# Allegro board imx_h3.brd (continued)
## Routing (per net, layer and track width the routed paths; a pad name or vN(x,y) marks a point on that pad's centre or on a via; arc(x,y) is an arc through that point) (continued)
USBOTG_OC: length 67.2
  TOP w0.1: v1(46.42,41.59) 47.67,41.59 48.64,42.56 v1(49.38,42.56)
  INT1 w0.1: v1(84.04,18.37) 84.04,19.53 81.65,21.92 69.06,21.92 68.12,22.86 62.09,22.86 62.08,22.85 61.41,22.85 60.7,23.57 59.87,23.57 58.99,23.57 57.17,25.4 56.99,25.4 v1(56.92,25.47)
  BOTTOM w0.1: v1(84.04,18.37) 84.04,16.43 85,15.47 85,13.02 84.94,12.96 ; U1.D4 52.64,43.41 52.36,43.13 51.98,43.13 51.97,43.14 51.65,43.14 51.45,42.94 51.45,42.74 51.13,42.43 50.89,42.43 50.59,42.13 50.59,41.83 50.41,41.65 49.92,41.65 49.55,42.03 49.55,42.4 v1(49.38,42.56) ; v1(46.42,41.59) 46.42,41.07 45.96,40.61 45.96,39.11 46.16,38.91 46.16,37.78 46.17,37.78 46.17,37.15 46.2,37.12 46.2,36.49 46.18,36.48 46.18,36.09 49.73,32.54 50.17,32.54 50.17,32.55 50.56,32.55 51.1,32.55 54.68,28.97 55.45,28.97 56.81,27.61 56.81,25.6 56.92,25.49 v1(56.92,25.47)
USBOTG_VBUS_EN: length 185.3
  TOP w0.1: v1(80.76,10.43) 80.76,19.36 80.16,19.96 80.16,20.17 v1(80.02,20.32) ; v1(36.77,23.81) 36.77,24.12 35.36,25.53 22.11,25.53 21.64,26 18.7,26 17.94,26.76 13.76,26.76 13.35,26.36 v1(13.15,26.36)
  INT1 w0.1: v1(44.72,70.62) 44.72,70.62 44.23,70.13 44.23,69.07 43.5,68.34 43.5,67.68 43.5,66.75 37.95,61.19 37.95,58 37.49,57.55 37.49,57.53 36.32,56.36 35.94,56.36 35.1,56.36 34.6,56.36 34.59,56.37 34.02,56.37 34.01,56.36 32.66,56.36 32.66,56.37 31.83,56.37 30.57,55.11 30.55,55.11 29.21,53.77 28.85,53.77 27.64,52.55 22.57,52.55 21.97,51.96 21.97,50.53 20.76,49.31 20.76,47.92 16.27,43.43 16.27,39.43 14.26,37.43 13.99,37.16 v1(13.99,37.04) 13.99,36.79 13.54,36.33 13.54,30.69 13.67,30.56 13.67,27.09 13.15,26.57 v1(13.15,26.36) ; v1(80.02,20.32) 78.85,21.49 69.31,21.49 68.11,20.28 63.91,20.28 63.58,20.28 63.14,20.73 61.89,20.73 61.45,21.17 39.8,21.17 37.16,23.81 v1(36.77,23.81)
  BOTTOM w0.1: U17.1 69.75,68.24 69.99,68.48 69.99,68.54 70,68.54 70,68.88 69.99,68.89 69.99,69.59 69.71,69.88 69.64,69.88 69.61,69.91 68.15,69.91 67.53,70.53 67.53,71.87 66.39,73.01 47.01,73.01 44.8,70.8 44.8,70.71 v1(44.72,70.62) ; v1(13.99,37.04) 14.07,37.04 14.14,37.12 14.41,37.12 16.23,35.29 16.23,33.99 U40.13 ; v1(80.76,10.43) 80.76,8.79 81,8.55 82,8.55 82.85,7.7 83.55,7.7 83.6,7.75 83.6,8.46 U33.3
VR_ANA: length 1.9
  BOTTOM w0.3: 25.59,66.69 25.56,66.71 C188.1 24.67,66.62 U4.44
VR_DIG: length 3.6
  BOTTOM w0.3: C189.1 27.28,66.32 C167.1 26.29,66.12 U4.45
VR_PA: length 5.3
  BOTTOM w0.3: C176.1 22.68,72.13 22.68,69.99 22.73,69.94 23.05,69.94 23.09,69.88 23.31,69.88 C174.1 23.65,69.52 C173.1 23.16,68.17 U4.42
WIFI_SDIO_CLK: length 8.6
  TOP w0.1: v1(19.44,35.83) 19.45,35.84 19.45,36.77 17.22,39 15.64,39 J20.25
  BOTTOM w0.1: R193.2 19.44,33.26 v1(19.44,35.83)
WIFI_SDIO_CMD: length 7.2
  TOP w0.1: J20.29 17.22,37.3 18.39,36.13 18.39,34.22 v1(18.12,33.95)
  BOTTOM w0.1: R64.2 18.12,34.65 v1(18.12,33.95) 18.12,33.46 R194.2
WIFI_SDIO_D0: length 7.3
  TOP w0.1: J20.23 16.83,39.7 19.25,37.28 19.25,37.28 19.79,36.75 19.79,36.22 v1(20.03,35.97)
  BOTTOM w0.1: v1(20.03,35.97) 20.03,35.05 R195.2
WIFI_SDIO_D1: length 5
  TOP w0.1: v1(18.82,35.88) 18.82,35.99 16.71,38.1 J20.27
  BOTTOM w0.1: v1(18.82,35.88) 18.86,35.88 R196.2
WIFI_SDIO_D2: length 6.9
  TOP w0.1: v1(21.27,36.64) 21.27,36.64 21.27,36.69 22.23,37.64 23.69,37.64 J20.28
  BOTTOM w0.1: R197.2 20.54,33.28 20.54,35.66 21.27,36.41 21.27,36.63 v1(21.27,36.64)
WIFI_SDIO_D3: length 3.9
  TOP w0.1: J20.30 22.13,36.9 21.52,36.28 v1(21.52,36.06)
  BOTTOM w0.1: R198.2 21.14,35.11 21.14,35.69 v1(21.52,36.06)
WL_RF_1V8: length 11
  TOP w0.1: 15.48,47.78 J20.11
  TOP w0.3: J20.11 14.05,47.7 C214.1 C151.1 12.2,48.55 12.2,51.92 13.14,52.87 v1(13.32,52.87)
  BOTTOM w0.3: v1(13.32,52.87) 13.32,53.04 13.7,53.41 U14.5 12.46,53.6 C199.1
WLAN_ACTIVE: length 118
  TOP w0.1: J20.49 14.14,29.3 12.88,30.56 v1(12.47,30.56)
  INT1 w0.1: v1(85.71,79.65) 85.46,79.4 84.09,79.4 82.83,78.15 82.83,75.15 80.38,72.69 79.35,72.69 78.91,72.25 71.95,72.25 71.5,72.69 63.86,72.69 63.86,72.7 62.65,72.7 62.65,72.69 46.26,72.69 45.89,72.33 44.7,72.33 36.7,64.32 36.7,58.29 36.67,58.27 36.67,58 35.83,57.16 34.94,57.16 34.92,57.17 34.34,57.17 34.34,57.18 33.68,57.18 33.66,57.16 33.01,57.16 33,57.16 32.32,57.16 32.32,57.17 31.99,57.17 31.49,57.17 30.23,55.91 30.22,55.91 28.88,54.57 28.52,54.57 27.31,53.35 23.56,53.35 23.06,53.35 22.73,53.35 22.73,53.35 22.22,53.35 21.16,52.29 21.16,50.99 19.95,49.78 19.95,48.25 12.76,41.06 12.76,40.75 12.74,40.74 12.74,33.24 12.43,32.92 12.43,30.62 v1(12.47,30.56)
  BOTTOM w0.1: R110.1 87.9,84.89 87.9,83 86.35,81.45 86.35,80.29 v1(85.71,79.65)
WLAN_PDN: length 79.5
  TOP w0.1: J20.22 24.85,40.1 26.75,42 26.75,50.28 28.56,52.1 28.68,52.23 28.73,52.28 v1(28.73,52.44)
  BOTTOM w0.1: U17.6 68.84,64.58 67.7,63.45 64.69,63.45 60.62,67.51 60.62,69.87 59.29,71.2 49.28,71.2 47.66,69.57 46.81,69.57 45.73,68.49 45.53,68.49 45.49,68.49 45.45,68.51 45.4,68.53 45.39,68.53 45.08,68.53 45.05,68.52 45.01,68.5 44.96,68.49 42.58,68.49 40.19,70.88 39.14,70.88 39.08,70.83 36.87,70.83 35.84,69.81 35.6,69.81 35.52,69.73 33.33,69.73 29.6,66 29.6,65.94 29.51,65.84 29.51,65.82 29.49,65.81 29.49,58.58 29.13,58.22 28.55,57.64 28.55,56.63 27.69,55.76 27.69,53.76 28.73,52.71 v1(28.73,52.44)
WLAN_WAKE: length 76.6
  TOP w0.1: v1(13.99,40.6) 14.11,40.6 14.21,40.5 J20.21
  INT1 w0.1: v1(13.99,40.6) 13.99,41.44 20.55,48.01 20.55,49.4 21.77,50.61 21.77,51.87 21.77,51.88 21.77,52.04 22.48,52.75 22.98,52.75 27.56,52.75 28.77,53.97 29.13,53.97 30.47,55.31 30.48,55.31 31.74,56.57 32.08,56.57 32.08,56.56 32.74,56.56 32.75,56.56 33.92,56.56 33.94,56.57 34.09,56.57 34.09,56.57 34.67,56.57 34.68,56.56 35.18,56.56 35.52,56.56 36.24,56.56 37.29,57.61 37.29,57.63 37.74,58.08 37.74,61.34 43.3,66.9 43.3,67.6 43.3,67.6 43.3,68.48 44.03,69.22 44.03,70.54 44.94,71.44 47.32,71.44 v1(47.7,71.06)
  BOTTOM w0.1: v1(47.7,71.06) 47.7,71.09 48.62,72 59.3,72 59.31,72 59.63,72 60.84,70.78 61.52,70.11 61.52,67.84 64.32,65.03 U17.12
ZB_SPI_MISO: length 46.8
  INT1 w0.1: v1(84.94,56.94) 84.94,56.94 85.47,56.4 86.3,56.4 88.1,54.6 88.1,52.34 88.11,52.34 88.11,50.09 93.84,44.35 95.1,44.35 96.12,45.37 v1(97.56,45.37)
  BOTTOM w0.1: RN8.2 75.68,73.12 77.23,71.57 77.23,70.75 79.86,68.12 79.86,66.71 80.22,66.34 80.22,66.28 80.23,66.28 80.23,65.59 80.22,65.59 80.22,64.99 81.29,63.92 81.29,60.88 84.94,57.23 v1(84.94,56.94) ; U15.29 102.03,44.6 101.8,44.84 100.76,44.84 100.1,45.49 U15.34 98.8,45.49 98.69,45.37 v1(97.56,45.37)
ZB_SPI_MOSI: length 47.6
  INT1 w0.1: v1(84.6,56.05) 84.85,55.8 85.3,55.8 85.6,55.5 86.6,55.5 87.7,54.4 87.7,52.12 87.71,52.12 87.71,49.92 93.7,43.93 95.4,43.93 95.78,44.3 96.9,44.3 98.45,42.75 99.16,42.75 99.18,42.76 v1(99.65,42.76)
  BOTTOM w0.1: RN8.4 76.04,72.12 76.81,71.35 76.81,70.59 79.45,67.95 79.45,66.84 79.46,66.54 79.82,66.18 79.82,66.11 79.83,66.1 79.83,65.76 79.82,65.76 79.82,65.56 79.82,64.83 80.89,63.76 80.89,60.71 84.14,57.46 84.14,56.71 84.6,56.25 v1(84.6,56.05) ; U15.28 102.5,44.1 102.5,43.81 101.45,42.76 v1(99.65,42.76)
ZB_SPI_SCK: length 49
  INT1 w0.1: v1(102.37,43.11) 102.34,43.11 99.92,45.54 98.04,45.54 97.7,45.88 96.33,45.88 95,44.55 93.93,44.55 88.31,50.17 88.31,52.42 88.3,52.43 88.3,54.75 86.45,56.6 86,56.6 85.59,57.01 v1(85.54,57.01)
  BOTTOM w0.1: RN8.1 75.64,73.62 77.43,71.84 77.43,70.84 80.06,68.21 80.06,66.79 80.42,66.43 80.42,66.37 80.43,66.36 80.43,65.51 80.42,65.5 80.42,65.07 81.49,64 81.5,64 81.5,63.84 81.49,63.84 81.49,60.96 85.44,57.01 v1(85.54,57.01) ; U15.27 103.03,43.77 v1(102.37,43.11)
ZB_SPI_SS: length 46.3
  INT1 w0.1: v1(85.85,55.95) 86.45,55.95 87.9,54.5 87.9,52.26 87.91,52.26 87.91,50 93.78,44.12 95.25,44.12 95.68,44.55 96.95,44.55 98.05,43.45 98.76,43.45 98.77,43.47 v1(99.22,43.47)
  BOTTOM w0.1: RN8.3 75.9,72.62 77.01,71.5 77.01,70.68 79.66,68.03 79.66,67.25 79.65,67.25 79.65,66.92 79.66,66.62 79.9,66.38 79.9,66.38 80.02,66.26 80.02,66.19 80.03,66.19 80.03,65.68 80.02,65.68 80.02,65.48 80.02,65.48 80.02,64.91 81.09,63.84 81.09,60.79 84.48,57.41 84.48,56.82 85.35,55.95 v1(85.85,55.95) ; v1(99.22,43.47) 99.66,43.47 99.77,43.57 101.46,43.57 101.53,43.65 U15.30
ZIGBEE_FLASH_ERASE: length 62.7
  TOP w0.1: v1(93.98,45.24) 92.65,45.24 91.4,46.5 91,46.5 88.79,48.7 85.4,48.7 82.2,51.9 82.2,57.6 81.15,58.65 v1(81.15,59.15)
  BOTTOM w0.1: v1(93.98,45.24) 94.1,45.36 95.71,45.36 96.79,44.28 96.8,44.28 97.8,43.28 97.8,42 98.6,41.2 104.5,41.2 104.78,41.48 106.72,41.48 107.51,42.26 108.98,42.26 110.43,43.71 110.86,43.71 110.96,43.81 111.14,43.81 111.56,44.24 111.56,44.62 111.88,44.94 112.93,44.94 R145.1 ; v1(81.15,59.15) 80.9,58.9 79.75,58.9 74.39,64.26 74.39,64.93 71.37,67.95 70.94,67.95 70.76,68.12 69.96,68.12 69.57,67.74 U17.2
ZIGBEE_GPIO: length 98.6
  TOP w0.1: v1(57.11,44.03) 57.02,44.03 56.69,43.71 56.69,42.91 56.89,42.71 56.89,41.91 56.23,41.25 55.71,41.25 54.86,40.4 53.35,40.4 50.14,37.19 44.91,37.19 v1(44.88,37.22)
  INT1 w0.1: v1(98.73,44.63) 99.66,44.63 100.07,44.22 100.07,42.46 98.5,40.89 98.5,39.67 v1(96.25,37.42) ; v1(89.3,24.11) 88.45,24.11 87.92,23.58 84.18,23.58 83.44,24.32 61.98,24.32 60.86,25.44 v1(60.73,25.44)
  BOTTOM w0.1: U15.33 98.94,44.98 98.73,44.78 v1(98.73,44.63) ; v1(57.11,44.03) 57.05,44.03 U1.E9 ; v1(89.3,24.11) 89.3,34.44 91.35,36.49 95.32,36.49 v1(96.25,37.42) ; v1(44.88,37.22) 45.1,37.22 45.59,36.75 45.59,35.83 49.47,31.94 50.41,31.94 50.41,31.95 50.8,31.95 54.41,28.34 54.7,28.34 55.46,27.57 55.46,27.13 55.99,26.6 55.99,26.59 56.52,26.06 56.52,25.25 56.8,24.97 60.27,24.97 v1(60.73,25.44)
ZIGBEE_LED: length 66.8
  TOP w0.1: v1(85.7,78.3) 85.55,78.45 84,78.45 83.75,78.2 83.75,76.05 82.45,74.75 82.45,58.7 82.1,58.35 82.1,58 82.45,57.65 82.45,51.95 85.5,48.9 89,48.9 91.15,46.75 91.55,46.75 91.8,46.5 v1(92.8,46.5)
  BOTTOM w0.1: R102.1 90.35,86.48 90.35,85 88.9,83.55 88.9,83.3 86.9,81.3 86.9,79.35 85.85,78.3 v1(85.7,78.3) ; U15.26 103.53,43.13 102.65,42.25 98.8,42.25 98.65,42.4 98.65,43.4 95.9,46.15 93.1,46.15 93,46.25 93,46.3 v1(92.8,46.5)
ZIGBEE_RESET_B: length 66
  TOP w0.1: v1(77.4,59.92) 77.4,59.6 81.05,55.95 81.05,51.15 83.77,48.44 83.77,48.43 83.81,48.38 83.81,48.38 83.99,48.2 84,48.2 85.09,47.1 87.5,47.1 88.54,46.06 R146.2 ; v1(103.59,54.09) 103.66,54.16 104.23,54.16 106.78,51.62 106.78,46.75 102.21,42.17 98.51,42.17 97.58,43.1 96.15,43.1 95.22,44.03 91.15,44.03 90.62,44.55 89.55,44.55 88.92,45.18 R146.2 ; R146.2 R80.1
  BOTTOM w0.1: v1(77.4,59.92) 76.83,59.92 70.51,66.24 U17.5 ; v1(103.59,54.09) 103.48,54.19 101.95,54.19 101.57,53.81 101.57,53.36 U15.51
N20112384: length 11.8
  BOTTOM w0.3: R82.2 92.75,51.98 C156.1 93.79,52.26 L10.2 ; L10.2 98.06,50.49 U15.44 ; L10.2 96.5,52.46 96.5,55.18 C184.1
N20121042: length 13.1
  TOP w0.3: v1(92.71,51.04) 92.71,53.22 93.94,54.45 v1(93.94,54.53)
  BOTTOM w0.3: v1(93.94,54.53) 94.15,54.32 D6.A ; v1(92.71,51.04) 92.71,50.57 93.21,50.07 93.29,50.07 94.04,49.32 96.25,49.32 L10.1 96.91,49.99 U15.43
N20123696: length 6.1
  BOTTOM w0.3: U15.45 99.08,50.99 98.64,51.43 98.64,53.73 D6.C 98.05,54.43 97.5,54.99 97.5,55.79 97.55,55.85
N20135512: length 14
  TOP w0.1: v1(106.94,54.32) 106.94,54.25 106.59,53.9 106.59,52.81 111.02,48.38 v1(111.65,48.38)
  BOTTOM w0.1: R76.1 113.2,46.25 R145.2 ; R76.1 112.39,47.3 Q4.1 112.48,47.49 111.77,48.2 111.77,48.25 v1(111.65,48.38) ; R76.1 R75.1 ; U15.61 106.59,53.38 106.59,53.9 107.01,54.32 v1(106.94,54.32)
N20137474: length 6.4
  BOTTOM w0.1: U15.64 108.94,53.33 109.36,52.91 109.36,51.36 R77.1 109.96,50.8 111.32,49.44 111.68,49.44 Q4.3
N20150953: length 1.6
  BOTTOM w0.3: J12.1 106.33,66.26 C182.2
N20151194: length 10.4
  BOTTOM w0.3: U15.60 106.04,54.68 106.04,63.06 106.06,63.17 106.07,63.25 106.16,63.46 106.18,63.48 C181.1
N20157126: length 5.4
  BOTTOM w0.1: 101.21,58.23 100.46,57.48 100.46,54.96 100.87,54.54 100.87,53.5 U15.50
N20157653: length 3.1
  BOTTOM w0.1: Y5.3 100.2,55.44 100.2,54.7 100.53,54.37 U15.49
N20183643: length 13.7
  TOP w0.1: v1(41.58,46.25) v1(41.58,47.47)
  BOTTOM w0.1: R181.2 44.83,47.47 44.82,47.48 44.43,47.48 44.42,47.47 43.82,47.47 43.81,47.48 43.42,47.48 43.41,47.47 v1(41.58,47.47) 41.56,47.48 41.36,47.48 41.08,47.2 38.27,47.2 38.19,47.27 37.36,47.27 36.77,47.87 35.3,47.87 35.09,47.66 U3.12 ; v1(41.58,46.25) 41.54,46.21 R9.2
N20200163: length 8.5
  BOTTOM w0.1: 50.8,16.94 50.8,20.18 R6.2 52.51,20.34 C31.1 ; 50.8,16.94 50.8,16.25 52.02,15.03 T1.5 ; 50.8,16.94 T1.4
N20614471: length 2.2
  BOTTOM w0.3: C177.1 21.66,72.9 21.66,72.16 21.67,72.15 L6.2 21.67,71.39 L7.2
N20623476: length 1.5
  BOTTOM w0.3: L8.1 21.68,75.41 C194.1 21.66,74.65 C177.2
N20623914: length 1.5
  BOTTOM w0.3: L8.2 21.67,77.17 C179.1 21.67,77.91 L9.1
N20639994: length 1.5
  BOTTOM w0.3: 21.68,78.93 21.68,79.67 C180.1 21.67,80.41 C193.1
N20766165: length 1.4
  BOTTOM w0.1: R15.1 31.7,42.37 U3.24
N20769333: length 4
  BOTTOM w0.3: C33.1 30.46,47.48 C32.1 31.37,48.19 31.56,47.99 31.56,47.54 31.62,47.49 31.62,46.72 U3.6
N20787959: length 5.6
  BOTTOM w0.3: 62.24,41.24 62.24,40.95 62.24,40.95 62.24,39.84 62.24,39.84
  BOTTOM w0.5: 62.24,39.84 62.52,39.56 62.52,38.9 63.25,38.16 L2.1
N20788242: length 8.7
  BOTTOM w0.3: 63.48,40.38 63.48,41.6 63.05,42.03
  BOTTOM w0.35: 66.36,38.05 65.25,38.05 64.3,39 63.65,39 63.2,39.45 63.2,40.1 63.48,40.38
  BOTTOM w0.5: L2.2 66.65,37.76 66.36,38.05
N21052242: length 6.8
  TOP w0.1: v1(55.98,40.39) 55.89,40.39 55.3,39.8 54.61,39.8 54.24,39.8 53.92,39.48 53.92,38.98 53.52,38.57 53.52,38.48 R49.1
  BOTTOM w0.1: U1.B9 56.64,41.97 56.17,41.5 56.17,40.58 55.98,40.39 v1(55.98,40.39)
N21053866: length 6.9
  BOTTOM w0.1: 55.61,36.31 Y3.1 56.38,37.08 C142.2 56.5,37.57 56.97,38.04 57.69,38.04 58.45,38.8 58.58,38.8 58.92,39.14 58.92,40.01 59.03,40.11 59.03,40.16 59.05,40.18 59.05,41.24
N21053884: length 8.2
  BOTTOM w0.1: 59.05,42.03 59.35,41.73 59.35,40.2 59.23,40.08 59.23,40.03 59.12,39.93 59.12,37.65 C141.1 58.88,37.34 58.88,35.15 58.64,34.92 Y3.3
N21906184: length 22.6
  TOP w0.3: 11.59,10.88 11.59,9.69 11.62,9.66 ; 11.59,10.88 11.59,11.96 11.64,12.01 ; 11.59,10.88 8.66,10.88 8.59,10.82 ; 11.59,10.88 J5.1 ; J5.1 14.51,10.88 14.52,10.9 ; J5.1 11.88,11.8 ; J5.1 11.88,9.97
  TOP w0.4: F1.2 13.66,17.42 ; F1.2 14.61,16.77 ; F1.2 12.71,16.77 ; F1.2 13.66,16.12 ; 15.01,16.7 C107.1 ; C107.1 15.61,17.61 ; C107.1 15.61,15.79
  PWR w0.3: J5.1 11.88,11.8 ; J5.1 11.88,9.97 ; J5.1 9.38,10.88 ; J5.1 14.39,10.88
  vias: v1(7.69,9.59) v1(7.68,5.92) v1(7.68,2.16) v1(11.1,13.88) v1(11.1,12.88) v1(11.59,7.99) v1(11.58,2.04) v1(12.1,17.3) v1(15.1,14.88) v1(15.1,12.88) v1(15.28,9.44) v1(15.45,5.74) v1(15.45,2.03) v1(15.82,11.38) v1(15.9,14.05)
N22010545: length 1.5
  BOTTOM w0.1: 106.19,42.82 106.19,42.87 106.56,43.24 106.56,44.11 U15.20
N22878041: length 0.8
  TOP w0.1: R41.2 65.52,18.42 C108.2
N22880531: length 22.6
  TOP w0.1: R41.1 66.44,20.19 66.46,20.21 66.51,20.21 67.37,19.34 67.52,19.34 67.67,19.19 67.67,15.51 70.2,12.99 70.2,2.04 SW2.1
N24090083: length 14
  TOP w0.1: v1(53.53,36.59) 53.54,36.58 55.45,36.58 56.98,38.11 56.98,38.48 56.96,38.5 56.96,39.07 57.27,39.37 57.27,40.91 57.78,41.43 57.78,42.86 57.91,42.99 v1(57.91,43.22)
  BOTTOM w0.1: U1.D11 58.24,43.56 v1(57.91,43.22) ; v1(53.53,36.59) 52.6,37.51 Y2.1 50.5,37.51 C143.1
N24109192: length 13.6
  TOP w0.1: v1(53.49,35.77) 53.49,35.81 54.06,36.38 55.53,36.38 57.41,38.26 v1(57.41,38.44)
  BOTTOM w0.1: v1(53.49,35.77) 53.49,35.72 52.78,35.01 Y2.2 51.89,34.93 50.32,34.93 C144.1 ; v1(57.41,38.44) 57.37,38.48 57.37,38.85 57.73,39.21 57.73,41.09 57.75,41.11 57.75,41.36 57.73,41.38 57.73,41.89 57.75,41.91 57.75,42.27 58.24,42.76 58.24,42.84
N24612024: length 2.9
  BOTTOM w0.3: ANT1.1 110.16,63.68 C181.2
N25260991: length 6
  TOP w0.3: 118,18.59 117.5,18.09 C304.1 ; 118,18.59 119.37,18.59 J7.1 ; 118,18.59 116.15,18.59 115.6,18.05 L3.2
N25368576: length 1.9
  BOTTOM w0.1: R78.2 108.17,44.26 U15.17
N25879518: length 7.8
  BOTTOM w0.3: C193.2 19.54,80.44 L30.1 arc(17.08,79.43) 16.06,76.98 J10.1
N25882006: length 98.2
  BOTTOM w0.1: 21.64,81.63 21.64,81.62 C191.1
  BOTTOM w0.3: C192.1 23.49,80.51 23.49,82.04 23.44,82.09
  BOTTOM w1: 23.44,82.09 arc(23.74,82.8) 24.44,83.09 46.15,83.09 arc(49.18,84.34) 50.43,87.36 50.43,89.03 arc(49.13,92.16) 46,93.46 13.12,93.46 arc(9.91,92.13) 8.58,88.92 8.58,87.73 arc(10.02,84.26) 13.49,82.82 20.44,82.82 arc(21.29,82.47) 21.64,81.63
N25942077: length 1.2
  BOTTOM w0.1: R125.1 109.08,48.98 U15.8
N26302633: length 5.9
  BOTTOM w0.1: U19.25 99.5,33.19 96.75,30.44 96.75,29.97 96.36,29.58 96.36,29.32 R199.2
N26303165: length 5.6
  BOTTOM w0.1: U19.26 99.43,33.69 96.28,30.54 R200.2
N26303698: length 7.3
  BOTTOM w0.1: 101.31,32.54 101.31,32.07 101.15,31.91 100.73,31.91 R201.2
N26304232: length 6.3
  BOTTOM w0.1: R202.2 96.86,28.34 100.81,32.3 U19.24
N26306493: length 9
  BOTTOM w0.1: U19.21 102.31,32.03 101.99,31.71 100.93,31.71 96.79,27.58 96.79,27.12 R203.2
N26311614: length 7.1
  TOP w0.3: v1(103.81,38.55) 103.76,38.59 103.01,38.59 102.81,38.39 102.81,38.05 102.47,37.71 102.47,35.46 L12.2
  BOTTOM w0.3: v1(103.81,38.55) 103.76,38.59 103,38.59 102.8,38.79 ; U19.5 102.8,37.35 102.8,38.28 102.81,38.29 102.81,38.59 102.82,38.6 102.82,38.72 102.8,38.74 102.8,38.79 ; 102.8,38.79 C61.1
N26315679: length 3
  TOP w0.3: R128.2 100.53,35.74 v1(99.28,35.74)
  BOTTOM w0.3: U19.30 99.33,35.69 v1(99.28,35.74)
N26322683: length 1
  BOTTOM w0.3: C68.1 103.86,32.49 U19.18
N26324953: length 1.1
  BOTTOM w0.3: C82.1 105.66,36.19 U19.10
N26335790: length 7.6
  TOP w0.3: v1(105.73,34.94) 105.81,34.85 105.81,28.56 TP12.1
  BOTTOM w0.3: v1(105.73,34.94) 105.73,34.97 105.51,35.19 U19.12
N26335836: length 7.2
  BOTTOM w0.3: TP11.1 107.24,39.71 107.24,36.86 106.07,35.69 U19.11
N26352753: length 5.9
  BOTTOM w0.1: R134.1 95.05,38.08 R129.1 97.97,38.08 99.86,36.19 U19.31
N26353356: length 2.7
  BOTTOM w0.1: R130.1 99.68,39.01 99.49,38.83 99.49,37.56 100.16,36.89 U19.32
N27366059: length 1.1
  TOP w0.3: R42.1 69.72,40 C104.2
N27773305: length 10.9
  BOTTOM w0.1: 94.06,11.03 U20.6 ; U20.6 94.06,11.68 ; U20.6 93.58,11.35
  BOTTOM w0.3: 92.39,11.25 D12.A ; D12.A 91.6,11.91 ; D12.A 93.17,11.91 ; D12.A 92.39,12.19 L20.2 ; L20.2 93.75,14.67 ; L20.2 95.3,13.56 ; L20.2 93.75,12.44 ; L20.2 92.2,13.56
N27773317: length 2.5
  BOTTOM w0.1: U20.4 95.03,8.49 R132.2 95.81,8.16
N28006980: length 8.5
  TOP w0.1: Q14.3 76.43,35.53 v1(75.2,35.53) ; v1(72.07,34.22) 72.04,34.19 Q13.3
  BOTTOM w0.1: U30.4 76.25,34.38 75.2,35.43 v1(75.2,35.53) 74.52,35.53 73.63,36.42 Q9.1 73.5,36.34 73.5,36.09 72.03,34.63 72.03,34.25 v1(72.07,34.22)
N28006984: length 11.4
  TOP w0.3: Q6.5 74.61,31.76 Q5.5 ; Q6.5 Q6.6 Q6.1 Q6.2 Q6.5 ; Q5.5 Q5.2 Q5.1 Q5.6 Q5.5
N28007052: length 13.3
  TOP w0.1: Q13.6 74.51,34.26 Q14.6
  TOP w0.3: Q13.5 Q13.2 Q13.1 Q13.6 Q13.5 ; Q13.5 74.5,34.84 Q14.5 ; Q14.5 Q14.6 Q14.1 Q14.2 Q14.5
N28007071: length 12.8
  TOP w0.1: Q5.3 71.2,31.41 71.18,31.41 70.95,31.65 70.92,31.65 v1(70.83,31.73) ; v1(75.3,32.36) 76.48,32.36 Q6.3
  BOTTOM w0.1: R135.2 71.44,35.53 ; 71.44,35.53 Q9.3 ; 71.44,35.53 71.2,35.29 70.81,35.29 70.53,35.02 70.53,32.03 v1(70.83,31.73) 70.83,31.65 71,31.48 74.81,31.48 75.3,31.97 v1(75.3,32.36)
N28007120: length 2.1
  TOP w0.3: C204.1 79.32,33.26 79.48,33.43 v1(79.75,33.43)
  BOTTOM w0.3: v1(79.75,33.43) 79.62,33.55 U22.2
N28007130: length 9.2
  TOP w0.3: 78.32,33.88 78.32,33.5 C204.2 ; 78.32,33.88 78.91,34.47 79.52,34.47 D17.C ; 78.32,33.88 v1(78.32,33.92)
  BOTTOM w0.3: v1(78.32,33.92) 78.32,31.73 77.8,31.22 L16.1 78.43,31.84 78.43,33.7 79.1,34.38 79.1,34.7 U22.3
N28007178: length 3.6
  TOP w0.1: v1(78.05,38.5) 78.25,38.71 79.1,38.71 v1(79.16,38.76)
  BOTTOM w0.1: R149.2 78.05,38.79 v1(78.05,38.5) ; v1(79.16,38.76) 79.17,38.74 79.46,38.74 79.62,38.57 U22.9
N28007224: length 1.9
  BOTTOM w0.1: R149.1 77.76,40.25 79.26,40.25 C203.1
N28007244: length 4.7
  TOP w0.1: v1(80.9,41.15) 80.9,40.52 80.93,40.49
  BOTTOM w0.1: U22.10 80.12,38.06 80.34,38.27 80.34,38.79 81,39.44 81,41.04 v1(80.9,41.15)
N28007274: length 4.3
  TOP w0.1: v1(78.73,39.81) 79.29,40.37 79.31,40.37 79.41,40.47 R176.1 80.18,40.48 80.19,40.49
  BOTTOM w0.1: U22.8 79.12,38.2 78.75,38.58 78.75,38.93 78.87,39.04 78.87,39.68 v1(78.73,39.81)
N28567011: length 2.6
  BOTTOM w0.5: U28.5 22.11,39.96 L18.1
N28574144: length 2.9
  BOTTOM w0.5: U28.3 16.28,41.87 16.2,41.94 15.29,41.94 14.82,41.47 14.82,41.28 R172.2
N28583550: length 5.1
  BOTTOM w0.5: C219.2 18.88,43.1 R173.1 ; R173.1 19.61,43.16 19.61,43.56 19.95,43.91 C218.1 21.37,43.9 R174.2 ; R173.1 19.55,43.1 19.55,41.88 U28.4
N28633938: length 9.1
  TOP w0.5: 30.68,64.58 31.03,64.23 R175.1 C224.2 ; 30.68,64.58 30.74,64.58 30.87,64.45 30.93,64.41 31.14,64.2 31.14,63.94 30.95,63.74 R178.2 30.95,62.57 C223.1 ; 30.68,64.58 v1(30.64,64.58) ; v1(34.16,63.49) 33.89,63.76 U29.4
  BOTTOM w0.5: v1(30.64,64.58) 30.74,64.48 30.74,63.95 31.2,63.49 v1(34.16,63.49)
N28634078: length 2.6
  TOP w0.5: L19.1 35.25,63.71 U29.5
N28722713: length 5.1
  BOTTOM w0.5: 28.2,17.29 28.2,18.2 L21.2 28.85,18.85 C303.1 ; 28.2,17.29 28.19,17.3 ; 28.2,17.29 28.2,16 27.69,15.49 J22.A1
N28726188: length 8
  BOTTOM w0.1: C146.2 38.49,34.99 38.4,34.9 38.4,34.03 38.2,33.84 36.19,33.84 35.5,33.15 ; U25.32 35.05,32.7 35.5,33.15 ; R205.1 35.5,33.15
N28726198: length 5.8
  BOTTOM w0.1: 35.45,32.2 35.9,32.65 36.75,32.65 Y7.3 38.06,31.43 C145.1 ; 35.45,32.2 33.33,32.2 U25.33 ; 35.45,32.2 35.46,32.2 R205.2
N28726415: length 3
  BOTTOM w0.3: U25.35 33.89,31.2 34.13,30.97 34.13,30.31 34.79,29.65 R177.1
N28726934: length 2.1
  BOTTOM w0.1: 27.34,32.7 U25.14
  BOTTOM w0.3: 27.34,32.7 27.15,32.5 26.14,32.5 25.94,32.71 C225.1
N28727026: length 1.9
  BOTTOM w0.3: U25.34 34.11,31.7 C226.1
N28727439: length 3.1
  BOTTOM w0.1: U25.25 31.55,36.58 32.14,37.17 32.14,37.51 R137.2 32.14,38.28 R136.1
N28728688: length 3.5
  BOTTOM w0.1: R147.1 34.23,37.29 34.23,37.16 33.84,36.76 R138.2 33.84,36.62 33.84,35.49 33.32,34.97 33.32,34.71 U25.28
N28737757: length 4.3
  TOP w0.5: v1(84.59,14.97) 84.77,14.79 84.77,13.56 D4.A
  BOTTOM w0.3: v1(84.59,14.97) 84.55,14.97 84.35,14.77 84.35,13.02 84.29,12.96
N28745352: length 3.3
  TOP w0.1: J13.77 J13.75 J13.73
  TOP w0.3: R93.1 101.66,73.16 J13.73
N28745357: length 2
  TOP w0.1: 103.61,84.08 103.55,84.14 101.63,84.14
N28753815: length 3.4
  TOP w0.1: D7.C 103.59,16 103.59,15.16 102.88,14.45 102.88,14.36 102.49,13.97 U34.7
N28753820: length 2.9
  TOP w0.1: D8.C 105.48,15.84 103.96,14.31 U34.5
N28753851: length 1.7
  TOP w0.1: R68.2 103.68,18.65 D7.A
N28753854: length 1.6
  TOP w0.1: D8.A 105.48,18.65 R69.2
N28755364: length 3.1
  TOP w0.3: U34.2 105.91,14.54 106.15,14.78 107.32,14.78 C34.1 R19.2
N28758461: length 6.2
  TOP w0.3: L5.2 115.04,4.65 116.01,5.62 116.02,5.62 116.19,5.79 v1(117.05,5.79) 117.32,5.52 J8.1
  BOTTOM w0.3: v1(117.05,5.79) 117.63,5.79 C305.1
N28758635: length 1.1
  TOP w0.3: U34.10 101.41,11.19 R18.2
N28759486: length 2.9
  TOP w0.1: TP15.1 108.89,13.96 U34.1
N28759489: length 4
  TOP w0.1: TP16.1 106.87,16.84 106.43,16.84 106.23,16.64 106.23,15.67 105.26,14.7 U34.3
N28774283: length 5.9
  TOP w0.15: J8.2 117.97,5.97 117.56,6.38 115.23,6.38 114.55,5.7 114.07,5.7 L34.2
N28774290: length 6.3
  TOP w0.15: L34.3 114.12,6.64 117.66,6.64 118.62,5.68 J8.3
N28783725: length 2.6
  BOTTOM w0.1: R95.1 R141.1 31.05,36.59 U25.24
N28784781: length 3
  BOTTOM w0.1: 28.33,37.13 29.06,37.13 29.06,36.79 29.62,36.23 29.89,36.23 30.05,36.07 U25.22
N28787165: length 7.2
  BOTTOM w0.5: L24.2 80.83,16.42 79.52,16.42 78.74,15.64 C301.1 78.25,14.27 76.92,12.94 U35.1
N28847997: length 0.7
  BOTTOM w0.1: U40.10 U40.11
N28848006: length 6
  BOTTOM w0.1: U40.9 13.6,33.89 13.6,28.1 U40.6
N28853722: length 6.1
  BOTTOM w0.1: 25.39,31.41 27,31.41 27.29,31.7 U25.12 ; 25.39,31.41 25.5,31.3 25.5,30.51 R108.1 ; 25.39,31.41 24.35,31.41 24.23,31.28 24.23,30.46 U31.2
N28858706: length 8.1
  TOP w0.1: SW5.1 91.36,2.15 91.36,5.05 89.45,6.95 R144.2
N28858725: length 7.4
  TOP w0.1: SW7.1 SW7.3 106.94,100.8 R127.2
N28859319: length 8.2
  TOP w0.1: R153.1 99.9,6.53 100.17,6.53 102.44,4.26 102.44,2.41 100.98,0.96 SW8.2
N28870429: length 6.2
  BOTTOM w0.3: D11.A 88.82,49.5 L11.2 88.11,49.6 U16.6
N28870443: length 2.1
  BOTTOM w0.3: R98.2 88.28,55.82 R103.1 88.11,55.73 U16.4
N28879486: length 27.1
  TOP w0.1: R121.2 90.62,70.49 90.3,70.81 90.09,70.81 90.09,70.82 v1(90.09,70.82) 90.08,70.81 89.87,70.81 89.54,70.49 R118.2 ; v1(93.87,87.92) 93.87,88.18 96.17,90.48 S1.2
  BOTTOM w0.1: v1(90.09,70.82) 90.09,70.82 90.07,70.84 90.07,77.5 90.56,77.99 90.56,82.26 91.05,82.75 91.05,82.75 91.54,83.24 91.54,85.56 93.65,87.67 93.65,87.7 v1(93.87,87.92)
N28886082: length 6.1
  BOTTOM w0.5: J22.B1 27.69,11.57 28.9,10.35 C302.1 29.84,9.51 30.3,9.05 L22.2
N28952872: length 88.5
  TOP w0.3: v1(86.23,102.47) 85.3,102.47 D38.1 D38.2 D37.1 D36.2 D35.1 D35.2 D42.1 D41.1 D41.2 D40.1 D40.2 D39.1 D39.2 11.26,102.72 11.23,102.7 10.82,102.7 D3.2
  BOTTOM w0.3: C296.1 86.22,90.55 L15.1 86.32,102.39 v1(86.23,102.47)
N28956999: length 38.5
  TOP w0.1: RN6.16 87.04,90.83 87.04,96.27 83.97,99.34 76.3,99.34 75.64,99.34 75.08,99.9 75.03,99.9 74.83,100.1 74.26,100.1 74.06,100.3 73.38,100.3 67.53,100.3 65.89,100.3 65.69,100.5 65.12,100.5 64.72,100.9 64.09,100.9 63.1,100.9 62.77,100.9 61.46,100.9 57.73,100.9 57.53,100.7 56.76,100.7 56.3,101.16 D35.4
N28957279: length 37.9
  TOP w0.1: RN6.15 87.59,90.83 87.59,96.04 86.98,96.65 86.94,96.65 84.05,99.54 76.22,99.54 75.72,99.54 75.16,100.1 75.11,100.1 74.91,100.3 74.34,100.3 74.14,100.5 73.46,100.5 67.61,100.5 67.61,100.5 66.92,100.5 65.97,100.5 65.77,100.7 65.21,100.7 65.12,100.79 65.12,100.87 64.89,101.1 64.18,101.1 63.02,101.1 61.37,101.1 57.32,101.1 D35.3
N28957286: length 30
  TOP w0.1: D36.4 65.97,100.9 65.97,100.79 66.06,100.7 66.83,100.7 72.38,100.7 74.22,100.7 74.42,100.5 74.99,100.5 75.19,100.3 75.24,100.3 75.8,99.74 76.14,99.74 84.14,99.74 87.03,96.85 87.46,96.85 88.09,96.21 88.09,90.83 RN6.14
N28957291: length 29.7
  TOP w0.1: RN6.13 88.59,90.83 88.59,96.25 87.79,97.05 87.11,97.05 84.22,99.94 75.89,99.94 75.33,100.5 75.27,100.5 75.07,100.7 74.51,100.7 74.31,100.9 73.63,100.9 67.78,100.9 66.82,100.9 66.45,101.28
N28957296: length 21.9
  TOP w0.1: 74.89,101.28 75.27,100.9 75.27,100.79 75.36,100.7 75.41,100.7 75.97,100.14 84.3,100.14 87.17,97.27 88.38,97.27 89.1,96.55 89.1,90.83 RN6.12
N28957304: length 21.7
  TOP w0.1: D37.3 76.68,100.34 84.38,100.34 87.25,97.47 88.94,97.47 89.6,96.81 89.6,90.83 RN6.11
N28958157: length 14.1
  TOP w0.1: RN6.10 90.1,90.83 90.1,97.04 89.47,97.67 87.34,97.67 84.2,100.81 D38.4
N28958172: length 14.3
  TOP w0.1: D38.3 85.05,100.25 87.42,97.88 89.94,97.88 90.65,97.17 90.65,90.83 RN6.9
N28958816: length 71.8
  TOP w0.1: D39.4 19.47,100.9 19.47,100.79 19.56,100.7 20.33,100.7 20.53,100.9 27.52,100.9 27.92,100.5 28.49,100.5 28.69,100.3 36.86,100.3 37.06,100.1 37.63,100.1 37.83,99.9 39.26,99.9 39.46,100.1 45.79,100.1 46.19,99.7 46.76,99.7 46.96,99.5 55.13,99.5 55.33,99.3 55.89,99.3 56.09,99.1 58.2,99.1 58.4,99.3 64.06,99.3 64.46,98.9 65.03,98.9 65.23,98.7 73.4,98.7 73.6,98.5 74.16,98.5 74.36,98.3 74.42,98.3 74.98,97.73 76.14,97.73 76.14,97.73 81.84,97.73 82.07,97.5 RN7.16
N28958825: length 71.1
  TOP w0.1: D39.3 20.12,101.1 27.61,101.1 28.01,100.7 28.57,100.7 28.77,100.5 36.94,100.5 37.14,100.3 37.71,100.3 37.91,100.1 39.18,100.1 39.38,100.3 45.88,100.3 46.28,99.9 46.84,99.9 47.04,99.7 55.21,99.7 55.41,99.5 55.98,99.5 56.18,99.3 58.11,99.3 58.31,99.5 64.14,99.5 64.54,99.1 65.11,99.1 65.31,98.9 73.48,98.9 73.68,98.7 74.25,98.7 74.45,98.5 74.5,98.5 75.06,97.93 76.06,97.93 76.06,97.94 81.92,97.94 82.62,97.23 RN7.15
N28958831: length 63.1
  TOP w0.1: RN7.14 83.12,97.02 82.01,98.14 75.97,98.14 75.97,98.13 75.15,98.13 74.58,98.7 74.53,98.7 74.33,98.9 73.76,98.9 73.56,99.1 65.39,99.1 65.19,99.3 64.63,99.3 64.23,99.7 63.6,99.7 58.23,99.7 58.03,99.5 56.26,99.5 56.06,99.7 55.49,99.7 55.29,99.9 47.13,99.9 46.93,100.1 46.36,100.1 45.96,100.5 39.3,100.5 39.1,100.3 37.99,100.3 37.79,100.5 37.22,100.5 37.02,100.7 28.86,100.7 28.77,100.79 28.77,100.9 D40.4
N28958836: length 62.6
  TOP w0.1: RN7.13 83.62,96.8 82.09,98.33 75.89,98.33 75.89,98.33 75.23,98.33 74.66,98.9 74.61,98.9 74.41,99.1 73.84,99.1 73.64,99.3 65.48,99.3 65.28,99.5 64.71,99.5 64.31,99.9 63.68,99.9 58.15,99.9 57.95,99.7 56.34,99.7 56.14,99.9 55.58,99.9 55.38,100.1 47.21,100.1 47.01,100.3 46.44,100.3 46.04,100.7 39.22,100.7 39.02,100.5 38.07,100.5 37.87,100.7 37.31,100.7 37.11,100.9 29.62,100.9 D40.3
N28958844: length 54.7
  TOP w0.1: RN7.12 84.13,96.81 82.41,98.53 75.81,98.53 75.81,98.53 75.31,98.53 74.75,99.1 74.69,99.1 74.49,99.3 73.93,99.3 73.73,99.5 65.56,99.5 65.36,99.7 64.79,99.7 64.39,100.1 63.76,100.1 63.43,100.1 63.1,100.1 61.79,100.1 58.06,100.1 57.86,99.9 56.43,99.9 56.23,100.1 55.66,100.1 55.46,100.3 47.29,100.3 47.09,100.5 46.52,100.5 46.12,100.9 39.13,100.9 38.93,100.7 38.16,100.7 38.07,100.79 38.07,100.9 D41.4
N28958860: length 54.1
  TOP w0.1: RN7.11 84.63,96.8 82.7,98.73 75.73,98.73 75.73,98.73 75.39,98.73 74.83,99.3 74.78,99.3 74.58,99.5 74.01,99.5 73.81,99.7 73.13,99.7 65.64,99.7 65.44,99.9 64.88,99.9 64.48,100.3 63.84,100.3 63.35,100.3 63.35,100.3 63.02,100.3 61.7,100.3 57.98,100.3 57.78,100.1 56.51,100.1 56.31,100.3 55.74,100.3 55.54,100.5 47.37,100.5 47.17,100.7 46.61,100.7 46.21,101.1 38.72,101.1 D41.3
N28958863: length 46.3
  TOP w0.1: 46.99,101.28 47.37,100.9 47.37,100.79 47.46,100.7 55.62,100.7 55.82,100.5 56.39,100.5 56.59,100.3 57.7,100.3 57.9,100.5 61.62,100.5 62.93,100.5 63.26,100.5 63.93,100.5 64.56,100.5 64.96,100.1 65.53,100.1 65.73,99.9 72.72,99.9 72.72,99.9 73.21,99.9 73.89,99.9 74.09,99.7 74.66,99.7 74.86,99.5 74.91,99.5 75.48,98.94 83.16,98.94 85.13,96.97 RN7.10
N28960141: length 46
  TOP w0.1: D42.3 48.22,100.9 55.71,100.9 55.91,100.7 56.47,100.7 56.67,100.5 57.62,100.5 57.82,100.7 61.54,100.7 62.85,100.7 63.18,100.7 64.01,100.7 64.64,100.7 65.04,100.3 65.61,100.3 65.81,100.1 67.08,100.1 67.08,100.1 67.45,100.1 73.3,100.1 73.98,100.1 74.18,99.9 74.74,99.9 74.94,99.7 75,99.7 75.56,99.14 79.83,99.14 83.56,99.14 85.68,97.01 RN7.9
N28976429: length 16.6
  TOP w0.1: J23.4 72.05,87.84 72.05,82.8 75.25,79.6 75.25,75.21 C242.2
  TOP w0.3: R97.2 73.01,87.11 J23.4
N28976672: length 9
  TOP w0.3: R97.1 74.03,87.28 J23.3
  BOTTOM w0.3: C200.2 75.68,86.98 J23.3 72.99,86.24 C197.2 72.96,85.86 R99.2 72.98,85.09 L27.2
N28977107: length 11
  BOTTOM w0.1: R99.1 74.49,85.11 75.66,83.94 75.98,83.94 76.78,83.14 78.91,83.14 L28.2
  BOTTOM w0.3: L28.2 79.77,85.17 C207.1 79.8,85.91 C209.1 79.84,87.9 J23.1
N28977635: length 2.8
  TOP w0.1: v1(76.2,73.65) 76.1,73.75 75.69,73.75 C242.1
  BOTTOM w0.1: v1(76.2,73.65) 76.75,73.1 R179.2
N29028813: length 8.1
  BOTTOM w0.1: R182.2 42.56,47.01 42.55,47 38.18,47 38.11,47.07 36.79,47.07 36.19,46.47 U3.13
N29028833: length 14.8
  TOP w0.1: v1(32.81,48.71) 32.82,48.71 33.1,48.71 33.16,48.66 37.66,48.66 v1(37.68,48.63)
  BOTTOM w0.1: v1(32.81,48.71) 33.01,48.5 33.01,48.46 33.09,48.39 U3.8 ; v1(37.68,48.63) 37.82,48.63 37.98,48.47 R183.2
N29028836: length 12.7
  TOP w0.1: v1(37.6,48.03) 37.23,48.4 33.08,48.4 32.98,48.3 32.51,48.3 v1(32.42,48.22)
  BOTTOM w0.1: U3.7 32.59,48.06 v1(32.42,48.22) ; v1(37.6,48.03) 37.61,48.03 37.84,48.26 41.19,48.26 41.47,47.99 R184.2
N29028839: length 5.3
  BOTTOM w0.1: R185.2 38.98,47.62 37.43,47.62 36.98,48.07 34.99,48.07 34.59,47.66 U3.11
N29028854: length 11.9
  TOP w0.1: v1(43.03,44.62) 43.26,44.62 45.13,46.49 v1(45.16,46.49)
  BOTTOM w0.1: U3.17 36.29,44.47 36.44,44.31 37.14,44.31 37.15,44.31 38.65,44.31 39.29,44.95 39.29,45.12 39.28,45.12 39.28,45.16 39.63,45.51 40.15,45.51 40.49,45.17 41.51,45.17 41.67,45.01 42.23,45.01 42.25,44.99 42.56,44.99 42.94,44.62 v1(43.03,44.62) ; R186.2 v1(45.16,46.49)
N29028859: length 10
  TOP w0.1: v1(42.94,45.92) 42.94,45.89 42.37,45.31 42.37,44.62 v1(42.39,44.59)
  BOTTOM w0.1: U3.18 36.28,43.97 36.43,44.11 37.23,44.11 38.73,44.11 39.48,44.87 39.48,45.08 39.72,45.31 40.06,45.31 40.3,45.08 40.3,44.97 41.42,44.97 41.59,44.81 41.99,44.81 41.99,44.81 42.15,44.81 42.37,44.59 v1(42.39,44.59) ; v1(42.94,45.92) 43.07,46.04 43.56,46.04 R187.2
N29028863: length 9
  BOTTOM w0.1: R188.2 43.4,44.96 43.17,45.18 42.66,45.18 42.65,45.19 42.33,45.19 42.31,45.21 41.76,45.21 41.59,45.37 40.58,45.37 40.23,45.72 39.55,45.72 39.08,45.25 39.08,45.03 38.57,44.51 37.06,44.51 37.06,44.51 36.55,44.51 36.09,44.97 U3.16
N29028931: length 17.4
  TOP w0.1: v1(36.74,46.38) 36.66,46.47 35.58,46.47 34.7,45.59 31.06,45.59 v1(31.02,45.55)
  BOTTOM w0.1: v1(36.74,46.38) 37.23,46.87 38.03,46.87 38.1,46.8 41.73,46.8 42.18,46.35 42.18,45.96 42.69,45.46 45.81,45.46 R180.2 ; v1(31.02,45.55) 31.02,45.53 31.05,45.53 31.48,45.97 U3.5
N29031770: length 7.7
  TOP w0.15: 111.81,19.91 112.28,19.91 112.39,19.79 119.43,19.79 J7.3
N29031779: length 7.7
  TOP w0.15: J7.2 119.43,19.14 111.91,19.14 111.81,19.03
N29031855: length 13.1
  BOTTOM w0.1: J17.2 66.78,31.81 68.86,31.81 70,32.95 70,35.54 70.98,36.53 71.34,36.53 73.75,38.94 73.75,39.3 R165.1
N29039241: length 4.3
  BOTTOM w0.1: U35.2 75.38,15.47 L33.3
N29039246: length 4.3
  BOTTOM w0.1: L33.2 75.32,16.34 U35.3
N29040204: length 3.8
  TOP w0.15: J22.A2 31.33,16.61 L31.2
N29040213: length 3.4
  TOP w0.15: L31.3 32.2,15.47 J22.A3
N29040310: length 4.8
  BOTTOM w0.15: L32.2 31.4,8.55 31.4,9.55 30.71,10.24 30.71,12.3 J22.B2
N29040319: length 4.8
  BOTTOM w0.15: 32.29,8.53 32.25,8.57 32.25,9.58 31.58,10.25 31.58,12.24 J22.B3
N29041995: length 54.1
  INT1 w0.1: v1(49.77,35.43) 49.39,35.43 48.9,35.93 48.85,35.93 48.54,36.24 48.18,36.24 47.46,36.95 47.46,36.95 45.98,38.44 45.98,38.44 44.4,40.01 44.4,40.02 43.07,41.35 42.67,41.35 40.85,41.35 40.24,41.96 39.92,41.96 39.38,42.5 37.25,42.5 37.11,42.35 34.87,42.35 33.8,43.43 31.48,43.43 30.4,42.35 28.34,42.35 26.62,40.63 25.87,40.63 23.76,38.53 23.76,35.54 23.76,31.49 22.44,30.17 19.74,30.17 v1(19.07,30.84)
  BOTTOM w0.1: 54.24,41.24 54.18,41.24 51.48,38.53 51.22,38.53 51.01,38.32 50.05,38.32 49.74,38.02 49.74,36.23 49.77,36.2 49.77,35.86 49.74,35.84 49.74,35.47 49.77,35.44 v1(49.77,35.43) ; v1(19.07,30.84) 18.88,31.03 18.88,31.42 19.27,31.81 19.29,31.81 R193.1
N29042001: length 53.3
  INT1 w0.1: v1(48.22,35.82) 48.22,35.91 47.27,36.87 47.27,36.87 45.9,38.24 45.89,38.24 44.2,39.93 44.2,39.94 42.99,41.15 42.59,41.15 40.77,41.15 40.16,41.76 39.84,41.76 39.3,42.3 37.34,42.3 37.19,42.15 34.76,42.15 33.69,43.22 31.56,43.22 30.48,42.15 28.42,42.15 26.7,40.43 25.95,40.43 23.96,38.45 23.96,35.62 23.96,31.41 22.5,29.94 19.06,29.94 18.45,30.56 18.45,31.06 v1(18.34,31.16)
  BOTTOM w0.1: R194.1 18.34,32.09 v1(18.34,31.16) ; v1(48.22,35.82) 48.22,36.05 47.74,36.53 47.74,38.03 48.41,38.69 48.87,38.69 49.76,39.58 50.73,39.58 50.73,39.57 50.9,39.57 50.9,39.58 51.1,39.58 52.64,41.12 52.64,41.24
N29042019: length 53.5
  INT1 w0.1: v1(19.44,31.41) 19.52,31.33 19.52,31.33 20.03,30.81 21.08,30.81 21.99,31.72 21.99,31.78 22.23,32.01 22.23,32.07 23.56,33.41 23.56,38.61 25.78,40.84 26.04,40.84 26.04,40.83 26.54,40.83 28.25,42.55 30.32,42.55 31.39,43.62 33.88,43.62 34.95,42.55 35.65,42.55 35.65,42.56 36.41,42.56 36.41,42.55 37,42.55 37.15,42.7 39.47,42.7 40,42.16 40.32,42.16 40.94,41.55 42.75,41.55 42.75,41.55 43.15,41.55 47.66,37.04 47.66,37.03 48.26,36.44 48.62,36.44 48.93,36.13 49.01,36.13 49.09,36.05 49.35,36.05 v1(49.37,36.03)
  BOTTOM w0.1: U1.B6 54.24,41.87 54.21,41.84 54.21,41.72 53.75,41.26 53.75,41.11 51.45,38.81 51.21,38.81 50.93,38.52 49.96,38.52 49.55,38.1 49.55,36.27 49.37,36.09 v1(49.37,36.03) ; 20,34.01 20,33.36 20.05,33.31 20.05,31.91 19.77,31.63 19.76,31.63 19.53,31.41 v1(19.44,31.41)
N29042022: length 50.1
  TOP w0.1: v1(53.84,42.37) 53.76,42.29 53.64,42.29 52.95,41.6 52.57,41.6 50.12,39.15 49.9,39.15 v1(49.9,39.14)
  INT1 w0.1: v1(49.9,39.14) 49.9,39.87 49.3,40.47 44.8,40.47 43.33,41.95 41.1,41.95 40.49,42.56 40.17,42.56 39.63,43.1 36.89,43.1 36.74,42.96 35.12,42.96 34.05,44.03 31.23,44.03 30.15,42.95 29.66,42.95 28.09,42.95 26.37,41.24 25.62,41.24 23.16,38.78 23.16,34.57 21.05,32.47 21.05,31.71 20.51,31.17 20.11,31.17 19.88,31.4 19.88,31.97 19.07,32.78 v1(19,32.78)
  BOTTOM w0.1: v1(53.84,42.37) 53.87,42.39 53.87,42.46 54.24,42.84 ; R196.1 18.86,33.7 19.05,33.51 19.05,32.82 v1(19,32.78)
N29042025: length 45.4
  INT1 w0.1: v1(20.28,31.57) 20.35,31.64 20.38,31.64 20.69,31.95 20.69,32.38 22.96,34.66 22.96,38.86 25.54,41.44 26.29,41.44 28.01,43.15 28.84,43.15 30.07,43.15 31.15,44.22 34.13,44.22 35.2,43.16 36.66,43.16 36.8,43.3 39.73,43.3 40.26,42.76 40.57,42.76 41.18,42.15 43.41,42.15 44.7,40.85 46.62,40.85 47.7,41.94 50.32,41.94 51.22,42.84 53.44,42.84 53.77,43.16 v1(53.77,43.24)
  BOTTOM w0.1: v1(20.28,31.57) 20.35,31.64 20.38,31.64 20.71,31.97 R197.1 ; U1.D6 54.24,43.59 53.88,43.24 v1(53.77,43.24)
N29042028: length 48.1
  INT1 w0.1: v1(21.51,31.9) 21.66,31.9 23.36,33.59 23.36,38.69 25.7,41.03 26.12,41.03 26.12,41.03 26.46,41.03 28.17,42.75 28.67,42.75 30.24,42.75 31.31,43.82 33.96,43.82 35.03,42.75 35.57,42.75 35.57,42.75 36.49,42.75 36.49,42.75 36.92,42.75 37.06,42.9 39.55,42.9 40.08,42.36 40.4,42.36 41.02,41.75 42.84,41.75 43.24,41.75 47.87,37.12 47.87,37.11 48.34,36.64 48.58,36.64 49.09,36.63 v1(49.13,36.59)
  BOTTOM w0.1: 53.45,41.24 53.37,41.24 52.22,40.09 52.21,40.09 50.84,38.72 49.88,38.72 49.34,38.19 49.34,36.84 49.13,36.63 v1(49.13,36.59) ; v1(21.51,31.9) 21.37,31.9 21.18,32.08 21.18,33.3 21.09,33.39 R198.1
N29085144: length 1.2
  TOP w0.3: C253.1 U42.4
N29085154: length 1.3
  TOP w0.1: U42.3 27.72,58.65 28.51,58.65 R210.2
N29116997: length 2.7
  TOP w0.1: v1(89.6,88.43) 89.6,89.4 RN6.6
  BOTTOM w0.1: v1(89.6,88.43) 89.6,87.72 R100.2 88.81,87.64 R101.2
N29117101: length 2.5
  TOP w0.1: v1(90.67,88.49) 90.67,89.42 RN6.8
  BOTTOM w0.1: R106.2 91.42,87.75 R102.2 90.67,87.81 v1(90.67,88.49)
N29117415: length 3.9
  TOP w0.1: v1(88.6,88.36) 88.6,89.41 RN6.4
  BOTTOM w0.1: 88.6,88.33 v1(88.6,88.36) 87.95,87.71 R107.2 R110.2
N29125794: length 2.8
  BOTTOM w0.1: R96.1 82.04,77.59 82,77.55 81.7,77.55 81.6,77.65 80.88,77.65 80.54,77.31 U41.13
N29128269: length 10.8
  TOP w0.5: 18.19,11.76 18.19,10.76 v1(18.27,10.69) ; 18.19,11.76 18.36,11.59 20,11.59 20.18,11.78 ; 18.19,11.76 C295.1 18.17,12.68 17.2,12.68 17.05,12.82 R20.1 ; 20.18,11.78 20.18,10.47 v1(20.25,10.41) ; 20.18,11.78 D45.A
  BOTTOM w0.5: v1(18.27,10.69) 18.51,10.69 Q15.3 20.25,11.05 v1(20.25,10.41)
N29155506: length 7.7
  TOP w0.1: SW6.2 95.23,2.06 95.23,6.07 93.97,7.34 R152.1
N29157230: length 2.8
  BOTTOM w0.1: 106.19,41.94 106.56,41.94 106.96,42.34 106.96,44.06 U15.19
N29241645: length 4.1
  TOP w0.1: v1(87.5,88.4) 87.6,88.5 RN6.2
  BOTTOM w0.1: R206.2 R207.2 87.5,88.01 v1(87.5,88.4)
N29243151: length 4.4
  TOP w0.3: R209.2 112.91,28.85 J16.1
  BOTTOM w0.3: C299.1 112.25,30.65 112.7,30.2 112.7,29.15 J16.1
N29246306: length 84.1
  TOP w0.1: R211.2 12.65,101.05 12.85,100.85 18.25,100.85 18.55,100.55 19.4,100.55 19.45,100.5 20.45,100.5 20.65,100.7 27.4,100.7 27.8,100.3 28.4,100.3 28.6,100.1 36.75,100.1 36.95,99.9 37.5,99.9 37.7,99.7 39.35,99.7 39.55,99.9 45.7,99.9 46.1,99.5 46.65,99.5 46.85,99.3 55,99.3 55.2,99.1 55.8,99.1 56,98.9 58.3,98.9 58.5,99.1 63.95,99.1 64.35,98.7 64.9,98.7 65.1,98.5 73.3,98.5 73.5,98.3 74.05,98.3 74.25,98.1 74.3,98.1 74.9,97.5 81.65,97.5 81.82,97.33 81.82,91.42 81.7,91.3 81.7,90.35 81.9,90.15 v1(81.9,90.05)
  INT1 w0.1: v1(81.45,86.45) 81.45,86.6 81.9,87.05 v1(81.9,90.05)
  BOTTOM w0.1: v1(81.45,86.45) 81.45,86.4 81.9,85.95 82.85,85.95 Q16.3
N29246425: length 1.4
  TOP w0.1: D3.3 11.82,101.28 R211.1
N29256208: length 1.7
  TOP w0.1: R46.2 10.79,101.46 10.79,101.28
N29272408: length 30.1
  BOTTOM w0.1: T1.12 55.37,1.35 44.5,1.35 43.4,2.45 43.4,2.55 41.55,4.4 41.55,13.25 42.45,14.15 42.45,14.3 43.06,14.91 R11.1
N29272682: length 19.1
  BOTTOM w0.1: R10.1 44.8,20.3 43.65,19.15 43.65,13.65 42.15,12.15 42.15,6.59 T1.9
N29297998: length 1.2
  BOTTOM w0.1: Q17.3 Q18.3
N29298001: length 1.2
  BOTTOM w0.1: Q20.3 107.22,14.44 Q19.3

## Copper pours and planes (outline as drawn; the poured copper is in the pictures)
3V3_GATED on TOP: 31.63,64.46 31.63,57.41 34.79,57.41 34.79,64.46
3V3_GATED on PWR: 96.09,26.72 96.09,42.62 89.41,49.3 89.41,50.48 86.63,53.26 86.63,61.15 82.16,65.62 72.59,65.62 70.09,68.12 70.09,69.1 69.09,70.1 34.97,70.1 32.48,67.62 32.48,65.54 33.52,64.51 36.68,64.51 36.68,51.81 36.7,51.81 36.7,47.94 39.23,45.4 39.23,44.5 28.51,44.5 28.51,48.65 14.35,48.65 14.35,28.43 10.9,28.43 10.9,45.74 10.86,45.74 10.86,54.48 26.91,54.48 26.91,70.37 30.2,73.66 70.15,73.66 70.15,90.03 91.17,90.03 91.17,104.8 109.62,104.8 109.62,54.21 123.09,54.21 123.09,37.06 105.34,37.06 105.34,63.65 104.06,63.65 104.06,68.84 103.94,68.84 103.94,54.21 102.76,54.21 102.76,48.6 100.13,45.98 100.13,33.12 104.67,33.12 104.67,26.72
3V3_ISM on PWR: 11.64,69.42 11.64,54.69 26.58,54.69 26.58,69.42
3V3_MAIN on TOP: 35.41,69.78 35.4,69.78 35.4,70.67 39.29,74.56 80.09,74.56 80.09,90 82.3,90 82.3,80.21 82.73,79.78 82.73,78.25 82.73,78.26 82.73,75.26 80.09,72.62 77.29,72.62 76.18,71.51 71.73,71.51 70.42,72.82 44.63,72.82 35.41,63.59 ; 1 cut-out
3V3_MAIN on TOP: 26.22,39.73 26.22,41.27 26.88,41.94 26.88,50.56 32.1,55.78 37.84,55.78 37.84,48.82 33.34,48.82 33.03,49.13 32.73,49.13 31.23,47.65 31.23,46.54 29.66,44.97 29.66,42.78 28.94,42.06 28.94,40.46 27.55,39.07 27.55,37.21 26.22,37.21 25.75,37.69 25.19,37.69 24.94,37.94 24.94,38.45
3V3_MAIN on BOTTOM: 29.66,65.78 29.66,54.18 33.47,54.18 35.36,56.07 35.36,59.11 32.32,59.11 32.12,59.31 32.12,63.17 31.08,63.17 30.56,63.69 30.56,65.04 33.97,68.45 36.81,68.45 36.81,70.5 36.54,70.5 35.66,69.62 33.5,69.62
3V3_MAIN on PWR: 19,37.89 19,43.46 25.91,43.46 26.34,43.03 26.34,39.86 28.81,37.38 38.59,37.38 40.23,35.74 40.23,32.56 36.22,28.55 26.19,28.55 26.19,32.04 20.34,37.89
4V2_BACKUP on TOP: 95.12,11.21 95.12,8.01 99.35,8.01 99.35,16.56 96.64,19.27 90.97,19.27 90.97,15.36
4V2_BACKUP on TOP: 73.23,36.62 73.23,37.4 79.38,43.54 83.29,43.54 83.29,41.82 79.77,41.82 76.52,38.57 76.52,37.6 75.53,36.62
4V2_BACKUP on TOP: 24.26,59.26 24.26,55.37 29.06,55.37 31.5,57.81 31.5,64.85 32.48,65.83 35.32,65.83 35.32,69.34 33.25,69.34 29.16,65.25 29.16,61.47 27.02,59.33 24.33,59.33 ; 1 cut-out
4V2_BACKUP on BOTTOM: 96.48,10.81 96.48,8.78 99.27,8.78 99.27,10.81
4V2_BACKUP on BOTTOM: 91.07,19.27 91.07,15.24 96.59,15.24 96.59,19.27
4V2_BACKUP on PWR: 85.57,40.72 85.57,10.53 98.76,10.53 98.76,18.1 104.67,18.1 104.67,26.54 95.73,26.54 95.73,30.12 90.99,30.12 89.52,31.6 89.52,36 88.25,37.26 88.25,43.03 85.9,45.37 85.9,49.79 83.62,52.07 79.52,52.07 79.52,45.41 78.47,44.35 78.44,44.35 75.89,41.81 84.48,41.81
4V2_BACKUP on PWR: 40.43,31.41 40.43,35.97 38.85,37.55 28.76,37.55 26.41,39.9 26.41,43.01 25.94,43.48 18.89,43.48 18.89,37.88 16.34,37.88 16.34,47.03 28.32,47.03 28.32,42.12 30.73,39.71 39.45,39.71 39.45,45.34 36.8,47.99 36.8,64.62 33.48,64.62 32.58,65.53 32.58,67.47 35.07,69.96 39.6,69.96 39.6,62.95 45.8,56.75 45.8,39.31 47.16,37.95 76.75,37.95 76.75,28.53 48.42,28.53 45.54,31.41
4V2_BUCK on TOP: 72.59,31.44 72.59,29.44 78.69,29.44 78.69,29.47 81.85,32.62 81.85,34.31 82.51,34.97 82.51,36.06 80.29,36.06 80.29,33.88 79.15,32.75 77.01,32.75 77.01,30.75 74.23,30.75 74.23,31.44
5V_MAIN on TOP: 10.78,24.85 10.78,18.13 16.78,18.13 16.78,2.03 26.03,2.03 26.03,20.35 20.75,20.35 20.75,24.58 20.48,24.85
5V_MAIN on BOTTOM: 10.89,20.62 10.89,10.05 19.81,10.05 19.81,17.99 14.25,17.99 13.91,18.33 13.91,19.26 12.55,20.62
5V_MAIN on PWR: 10.77,28.28 36.31,28.28 39.38,31.35 45.42,31.35 48.31,28.46 76.87,28.46 76.87,38.04 65.94,38.04 65.94,41.39 65.95,41.39 67.52,42.96 70.49,42.96 71.69,41.76 84.15,41.76 85.45,40.47 85.45,20.92 19.61,20.92 19.61,20.01 10.77,20.01
5V_USB on BOTTOM: 19.54,24.75 19.54,19.06 25.14,19.06 25.14,20.15 23.35,21.94 23.35,24.75
5V_USB on BOTTOM: 83.69,12.31 83.69,7.05 91.79,7.05 91.79,12.31
5V_USB on PWR: 55.67,6.59 55.67,14 55.63,14 55.63,18.72 44.77,18.72 44.77,14 19.88,14 19.88,20.67 85.41,20.67 85.41,10.47 98.76,10.47 98.76,3.36 86.47,3.36 86.47,6.59
GND on TOP (solid shape): 11.97,30.46 12.23,30.19 12.23,29.65 12.43,29.44 12.78,29.44 12.78,27.11 12.17,26.5 12.17,26.09 11.14,25.07 10.68,25.07 10.68,13.68 0.15,13.68 0.15,19.3 4.64,19.3 4.64,26.7 2.75,26.7 2.75,24.45 3.35,24.45 3.35,24.15 1.75,24.15 1.75,24.45 2.25,24.45 2.25,27.27 4.61,27.27 5.79,26.36 8.85,26.36 9.73,27.04 12.51,27.04 12.51,29.15 9.83,29.15 9.03,29.77 8.96,29.77 8.96,30.02 8.62,30.02 8.62,29.7 8.63,29.7 8.63,29.27 8.45,29.27 8.45,29.7 8.46,29.7 8.46,30.02 7.79,30.02 7.79,29.77 6.79,29.77 6.79,30.02 6.39,30.02 6.39,29.77 6.39,29.77 6.39,29.27 6.2,29.27 6.2,29.77 6.19,29.77 6.19,30.02 5.79,30.02 5.79,29.77 4.72,28.95 1.99,28.95 1.99,28.2 4.72,28.2 5.19,28.56 6.29,28.56 6.29,28.56 6.59,28.56 6.59,28.56 7.24,28.56 7.24,27.57 5.21,27.57 4.72,27.95 1.74,27.95 1.74,28.8 0.64,28.8 0.64,28.8 0.2,28.8 0.2,37.47 0.3,37.57 11.97,37.57
GND on TOP (solid shape): 12.02,72.13 12.28,71.87 12.28,71.32 12.48,71.12 12.83,71.12 12.83,68.79 12.22,68.17 12.22,67.24 12.17,67.19 11,67.19 11,55.35 0.3,55.35 0.2,55.35 0.2,60.97 4.7,60.97 4.7,68.37 2.79,68.37 2.79,66.12 3.41,66.12 3.41,65.82 1.8,65.82 1.8,66.12 2.29,66.12 2.29,68.95 4.66,68.95 5.84,68.04 8.91,68.04 9.68,68.63 12.62,68.63 12.62,70.83 9.88,70.83 9.08,71.45 9.01,71.45 9.01,71.7 8.68,71.7 8.68,70.95 8.52,70.95 8.52,71.7 7.84,71.7 7.84,71.45 6.84,71.45 6.84,71.7 6.45,71.7 6.45,70.95 6.25,70.95 6.25,71.7 5.84,71.7 5.84,71.45 4.77,70.62 2.04,70.62 2.04,69.87 4.77,69.87 5.24,70.24 6.28,70.24 6.28,70.24 6.39,70.24 6.39,70.24 7.29,70.24 7.29,69.25 5.26,69.25 4.77,69.62 1.79,69.62 1.79,70.47 0.87,70.47 0.87,70.44 0.53,70.44 0.53,70.77 0.53,70.77 0.53,71.02 0.73,71.02 0.73,70.67 1.13,70.67 1.13,70.67 1.13,71.02 0.73,71.02 0.53,71.02 0.53,71.02 0.21,71.02 0.21,81.15 12.02,81.15
GND on BOTTOM (solid shape): 69.95,32.61 70.06,32.63 70.12,32.54 70.12,32.5 69.46,31.83 69.46,30.45 69.18,30.17 68.77,30.17 68.77,31.6 68.94,31.6
GND on BOTTOM (solid shape): 55.46,29.55 55.48,29.44 55.39,29.38 55.03,29.38 51.16,33.25 50.83,33.25 50.35,33.73 50.33,33.84 50.42,33.9 51.11,33.9
GND on BOTTOM (solid shape): 27.31,22.92 27.35,22.87 27.4,22.82 28.39,21.83 28.39,20.88 28.27,20.88 28.27,19.66 27.08,19.66 27,19.7 26.99,19.8 26.99,20.09 26.81,20.31 26.81,20.59 26.51,20.89 26.51,22.86 26.57,22.92
GND on BOTTOM (solid shape): 93.63,10.13 94.56,10.13 94.56,9.79 93.57,9.79 93.57,9.12 94.1,9.12 94.71,8.51 94.67,8.48 94.64,8.44 94.62,8.4 94.59,8.38 94.56,8.38 94.52,8.38 94.48,8.38 94.45,8.38 94.42,8.4 94.05,8.63 93.65,8.47 93.18,8.47 93.18,9.28 91.95,9.28 91.95,10.65 93.63,10.65
GND on BOTTOM (solid shape): 71.83,21.1 71.92,21.04 71.9,20.93 70.89,19.92 70.06,19.92 69.98,19.98 69.98,20.08 69.97,20.57 69.5,20.7 69.47,20.69 69.23,20.93 69.2,21.04 69.3,21.1
GND on BOTTOM (solid shape): 54.45,4.12 54.52,4.08 54.55,4.01 54.58,3.77 54.67,3.54 54.69,3.5 52.99,1.81 46.69,1.81 46.59,1.87 46.62,1.98 47.5,2.87 47.5,3.09 47.54,3.1 48.03,3.44 48.21,4.01 48.24,4.08 48.31,4.12
GND on BOTTOM (solid shape): 33.61,37.12 33.61,37.09 33.61,37.06 33.59,37.03 33.36,36.6 33.63,36.19 33.63,35.58 33.54,35.49 33.46,35.46 33.39,35.51 33.21,35.65 32.98,35.68 32.9,35.7 32.86,35.78 32.86,36.78 33.12,37.03 33.14,37.03 33.34,37.07 33.51,37.18 33.52,37.2 33.61,37.2
GND on BOTTOM (solid shape): 25.35,32.2 25.8,31.97 26.27,32.18 26.29,32.19 26.41,32.19 26.46,32.16 26.45,32.11 26.34,31.94 26.33,31.74 26.31,31.66 26.23,31.62 24.26,31.62 24.01,31.37 24.01,31.01 23.8,31.01 23.8,32.06 23.86,32.15 23.97,32.14 24.34,32.03 24.68,32.2
GND on BOTTOM (solid shape): 59.57,37.32 59.65,37.29 60.96,35.98 61.28,35.98 61.32,35.91 61.38,35.85 61.4,35.83 61.4,35.76 61.29,35.76 60.58,35.05 60.58,33.16 60.49,33.09 60.42,32.99 60.34,32.93 60.25,32.96 60,33.22 59.97,33.3 60.02,33.38 60.21,33.95 59.64,34.11 59.6,34.09 59.31,34.38 58.88,34.38 58.88,34.86 59.09,35.06 59.09,37.04 59.11,37.11 59.18,37.14 59.36,37.18 59.5,37.29
GND on BOTTOM (solid shape): 42.16,6.04 42.22,6.13 42.33,6.11 43.97,4.48 43.95,4.44 44.53,3.1 45.67,4.01 45.7,4.08 45.77,4.12 46.27,4.12 46.34,4.08 46.37,4.01 46.53,3.47 46.96,3.13 47.03,3.05 47,2.96 46.1,2.06 44.79,2.06 42.16,4.69
GND on BOTTOM (solid shape): 99.64,36.11 99.64,36.03 99.57,36.03 99.56,36.05 98.94,35.98 99.08,35.38 99.14,35.3 99.11,35.21 98.73,34.84 98.73,34.43 95.85,31.54 95.72,31.53 95.69,31.66 95.98,34.14 94.44,36.09 94.39,36.2 94.49,36.28 95.4,36.28 96.14,37.02 96.17,37.01 96.61,37.22 96.55,37.7 96.54,37.81 96.63,37.87 97.89,37.87
GND on BOTTOM (solid shape): 64.46,38.12 64.52,38.21 64.63,38.19 65.11,37.71 65.44,37.71 65.44,33.42 66.81,33.42 67.86,34.47 67.86,34.55 67.93,34.55 67.98,34.5 68.01,34.47 68.01,33.5 67.86,33.37 67.76,33.19 67.75,33.15 65.11,33.15 65.11,33.16 64.64,32.74 65.11,32.33 65.11,32.33 68.58,32.33 68.63,32.38 68.97,32.38 69.03,32.38 69.08,32.33 68.77,32.02 66.69,32.02 66.34,31.66 66.3,31.68 65.17,31.48 65.14,30.33 65.15,30.23 65.06,30.17 64.58,30.17 64.49,30.23 64.51,30.34 64.13,31.7 63.01,30.83 62.99,30.75 62.91,30.72 62.49,30.72 60.95,32.27 60.92,32.36 60.97,32.43 61.2,32.79 61,33.16 61,34.87 61.47,35.34 61.86,35.34 61.87,35.35 61.98,35.37 62.04,35.28 62.04,34.47 63.09,33.42 64.46,33.42
GND on BOTTOM (solid shape): 48.59,20.13 48.87,19.93 49.2,20.02 49.24,20.03 49.27,20.01 49.67,19.87 50.03,20.09 50.05,20.12 50.09,20.12 50.12,20.11 50.16,20.12 50.2,20.12 50.22,20.09 50.36,19.95 50.54,19.87 50.58,19.86 50.58,18.73 44.76,18.73 44.76,11.8 44.69,11.7 44.57,11.74 42.49,11.1 44.57,10.45 44.69,10.49 44.76,10.4 44.76,9.84 43.66,8.05 44.76,6.26 44.76,4.91 44.52,4.88 44.3,4.79 44.26,4.77 42.36,6.68 42.36,12.06 43.86,13.56 43.86,19.06 44.89,20.09 44.96,20.09 45.37,19.82 45.8,20.05 45.83,20.08 45.86,20.08 45.9,20.07 45.94,20.08 45.97,20.08 46,20.05 46.43,19.82 46.84,20.1 46.86,20.13
GND on TOP: 4.52,0.21 4.52,12.16 10.76,12.16 10.76,16 10.77,16 10.77,27.57 10.76,27.57 10.76,36.91 5.22,36.91 5.22,36.89 0.2,36.89 0.2,55.37 10.76,55.37 10.76,81.14 62.81,81.14 62.81,90.02 70.59,90.02 70.59,90.06 80.05,90.06 80.05,90.02 91.19,90.02 91.19,104.8 109.62,104.8 109.62,54.25 123.5,54.25 123.5,0.68 122.37,0.68 122.37,0.31 123.5,0.31 123.5,0.31 23.95,0.31 23.95,1.84 16.66,1.84 16.66,0.21 ; 90 cut-outs
